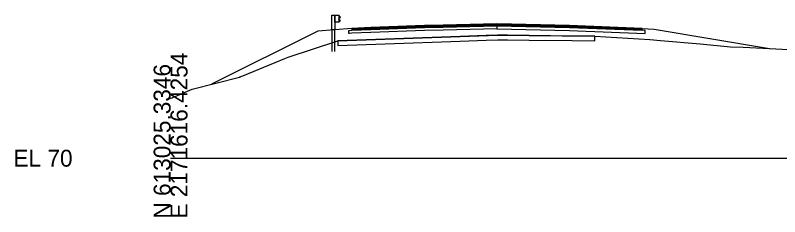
# Model space of a CAD drawing. Extents: x -26 to 1303, y -3010 to 12023.
# Drawn here: x -25.7 to 100.8, y 4990.3 to 5023.7 of the extents above; entities that cross this region are included whole.
import ezdxf

# ---------------------------------------------------------------- set-up
doc = ezdxf.new("R2010")
doc.units = 0
for name, color, linetype in [('RD_GPK_XS_Cell', 7, 'Continuous'), ('RD_PD_Final_TrvlWay', 7, 'Continuous'), ('RD_XS_Base', 7, 'Continuous'), ('RD_XS_ExGround', 7, 'Continuous'), ('RD_XS_ExPaveRet', 7, 'Continuous'), ('RD_XS_GR', 7, 'Continuous'), ('RD_XS_Greenside', 7, 'Continuous'), ('RD_XS_Pave', 7, 'Continuous'), ('RD_XS_PaveOvlay_CP', 7, 'Continuous'), ('RD_XS_TieSlope', 7, 'Continuous')]:
    doc.layers.add(name, color=color, linetype=linetype)

msp = doc.modelspace()

# ---------------------------------------------------------------- linework, layer by layer
at = {"layer": 'RD_GPK_XS_Cell'}
msp.add_line((0, 5000), (150, 5000), dxfattribs=at)
at = {"layer": 'RD_PD_Final_TrvlWay'}
msp.add_lwpolyline([(27.17, 5017.68), (27.17, 5021.28), (26.67, 5021.24), (26.67, 5017.68)], dxfattribs=at)
at = {"layer": 'RD_XS_Base'}
for p, q in [((29.5, 5020.8), (29.5, 5021.17)), ((29.5, 5021.17), (29.63, 5021.17)), ((29.63, 5021.17), (30, 5021.19)), ((30, 5021.19), (33.12, 5021.31)), ((33.12, 5021.31), (42, 5021.67)), ((42, 5021.17), (33.12, 5020.81)), ((42, 5021.67), (45.12, 5021.73)), ((45.12, 5021.23), (42, 5021.17)), ((45.12, 5021.73), (54, 5021.91)), ((54, 5021.41), (45.12, 5021.23)), ((54, 5021.95), (54, 5022.07)), ((54, 5022.07), (54, 5021.58)), ((54, 5021.91), (54, 5022.07)), ((54, 5022.07), (54, 5021.41)), ((54, 5021.91), (54, 5021.95)), ((54, 5021.91), (54, 5021.54)), ((54, 5021.91), (54, 5021.41)), ((66, 5021.67), (54, 5021.91)), ((54, 5021.91), (54, 5021.91)), ((54, 5021.58), (54, 5021.41)), ((54, 5021.54), (54, 5021.41)), ((54, 5021.41), (54, 5021.41)), ((54, 5021.41), (54, 5021.41)), ((54, 5021.41), (66, 5021.17)), ((78, 5021.19), (66, 5021.67)), ((66, 5021.17), (78.5, 5020.67)), ((68, 5021.59), (68, 5021.59)), ((78.5, 5021.17), (78, 5021.19)), ((78, 5021.19), (78, 5021.19)), ((78.5, 5020.67), (78.5, 5021.17)), ((78.5, 5021.17), (78.5, 5021.17)), ((29.5, 5020.67), (29.5, 5020.8)), ((29.63, 5020.67), (29.5, 5020.67)), ((30, 5020.69), (29.63, 5020.67)), ((33.12, 5020.81), (30, 5020.69)), ((68, 5021.09), (68, 5021.09)), ((78.5, 5020.67), (78.5, 5020.67)), ((78.5, 5020.67), (78.5, 5020.67))]:
    msp.add_line(p, q, dxfattribs=at)
at = {"layer": 'RD_XS_ExGround'}
msp.add_lwpolyline([(0, 5009.88), (3.56, 5011.44), (11.39, 5013.44), (11.48, 5013.46), (11.57, 5013.48), (11.61, 5013.51), (11.97, 5013.65), (17.3, 5015.84), (18.9, 5016.5), (19.46, 5016.71), (27.65, 5019.42), (47.94, 5020.15), (54.12, 5020.38), (59.35, 5020.32), (70.22, 5020.19), (79.28, 5019.64), (81.06, 5019.49), (87.61, 5018.94), (92.64, 5018.46), (94.72, 5018.38), (104.46, 5017.9)], dxfattribs=at)
at = {"layer": 'RD_XS_ExPaveRet'}
msp.add_lwpolyline([(59.35, 5020.32), (55.73, 5020.36), (54.12, 5020.38), (52.21, 5020.31), (47.94, 5020.15), (35.5, 5019.7), (27.65, 5019.42), (27.65, 5019.01), (27.65, 5018.67), (35.5, 5018.95), (47.94, 5019.4), (52.21, 5019.56), (54.12, 5019.63), (55.73, 5019.61), (59.35, 5019.57), (66.45, 5019.49), (70.22, 5019.44), (70.22, 5019.79), (70.22, 5020.19), (66.45, 5020.24), (59.35, 5020.32)], dxfattribs=at)
msp.add_lwpolyline([(59.35, 5020.32), (55.73, 5020.36), (54.12, 5020.38), (52.21, 5020.31), (47.94, 5020.15), (35.5, 5019.7), (27.65, 5019.42), (27.65, 5019.01), (27.65, 5018.67), (35.5, 5018.95), (47.94, 5019.4), (52.21, 5019.56), (54.12, 5019.63), (55.73, 5019.61), (59.35, 5019.57), (66.45, 5019.49), (70.22, 5019.44), (70.22, 5019.79), (70.22, 5020.19), (66.45, 5020.24), (59.35, 5020.32)], dxfattribs=at)
at = {"layer": 'RD_XS_GR'}
for p, q in [((26.67, 5021.24), (26.67, 5023.68)), ((26.67, 5023.68), (26.92, 5023.68)), ((26.92, 5023.68), (27.17, 5023.68)), ((27.17, 5023.68), (27.17, 5021.28)), ((27.17, 5022.51), (27.17, 5023.68)), ((27.17, 5023.68), (27.83, 5023.68)), ((27.83, 5023.68), (27.83, 5022.51)), ((28.03, 5023.46), (27.83, 5023.68)), ((27.83, 5023.68), (27.83, 5022.81)), ((27.83, 5022.51), (27.17, 5022.51)), ((27.83, 5023.09), (27.9, 5023.17)), ((28.03, 5022.88), (27.83, 5023.09)), ((27.83, 5022.81), (27.83, 5022.51)), ((27.83, 5022.51), (27.9, 5022.58)), ((27.9, 5023.17), (28.1, 5023.38)), ((27.9, 5022.58), (28.1, 5022.8)), ((28.1, 5023.38), (28.03, 5023.46)), ((28.1, 5022.8), (28.03, 5022.88)), ((27.17, 5021.28), (26.67, 5021.24))]:
    msp.add_line(p, q, dxfattribs=at)
at = {"layer": 'RD_XS_Greenside'}
for p, q in [((80, 5021.35), (99.09, 5018.16)), ((24.35, 5021.06), (6.79, 5012.28))]:
    msp.add_line(p, q, dxfattribs=at)
at = {"layer": 'RD_XS_Pave'}
for p, q in [((33.12, 5021.63), (30, 5021.51)), ((30, 5021.51), (30, 5021.39)), ((33.12, 5021.47), (30, 5021.35)), ((30, 5021.35), (33.12, 5021.47)), ((30, 5021.39), (30, 5021.35)), ((30, 5021.35), (30, 5021.23)), ((30, 5021.19), (33.12, 5021.31)), ((30, 5021.23), (30, 5021.19)), ((42, 5021.99), (33.12, 5021.63)), ((42, 5021.83), (33.12, 5021.47)), ((33.12, 5021.47), (42, 5021.83)), ((33.12, 5021.31), (42, 5021.67)), ((45.12, 5022.05), (42, 5021.99)), ((45.12, 5021.89), (42, 5021.83)), ((42, 5021.83), (45.12, 5021.89)), ((42, 5021.67), (45.12, 5021.73)), ((54, 5022.23), (45.12, 5022.05)), ((54, 5022.07), (45.12, 5021.89)), ((45.12, 5021.89), (54, 5022.07)), ((45.12, 5021.73), (54, 5021.91)), ((66, 5021.99), (54, 5022.23)), ((54, 5021.95), (54, 5022.07)), ((54, 5022.07), (54, 5021.95)), ((54, 5021.91), (54, 5022.07)), ((54, 5022.07), (66, 5021.83)), ((66, 5021.83), (54, 5022.07)), ((54, 5022.07), (54, 5021.91)), ((54, 5021.91), (54, 5021.95)), ((54, 5021.95), (54, 5021.91)), ((54, 5021.91), (54, 5021.91)), ((54, 5021.91), (54, 5021.91)), ((54, 5021.91), (66, 5021.67)), ((78, 5021.51), (66, 5021.99)), ((66, 5021.83), (78, 5021.35)), ((78, 5021.35), (66, 5021.83)), ((66, 5021.67), (78, 5021.19)), ((68, 5021.91), (68, 5021.91)), ((68, 5021.75), (68, 5021.75)), ((68, 5021.75), (68, 5021.75)), ((68, 5021.59), (68, 5021.59)), ((78, 5021.35), (78, 5021.51)), ((78, 5021.51), (78, 5021.51)), ((78, 5021.35), (78, 5021.35)), ((78, 5021.35), (78, 5021.35)), ((78, 5021.19), (78, 5021.35)), ((78, 5021.35), (78, 5021.35)), ((78, 5021.19), (78, 5021.19)), ((78, 5021.19), (78, 5021.19))]:
    msp.add_line(p, q, dxfattribs=at)
at = {"layer": 'RD_XS_PaveOvlay_CP'}
for p, q in [((30, 5021.51), (42, 5021.99)), ((42, 5021.99), (54, 5022.23)), ((54, 5022.23), (66, 5021.99)), ((66, 5021.99), (78, 5021.51))]:
    msp.add_line(p, q, dxfattribs=at)
at = {"layer": 'RD_XS_TieSlope'}
for p, q in [((30, 5021.51), (24.35, 5021.06)), ((78, 5021.51), (80, 5021.35))]:
    msp.add_line(p, q, dxfattribs=at)

# ---------------------------------------------------------------- texts
at = {"layer": 'RD_GPK_XS_Cell'}
for s, p in [('E 2171616.4254', (2.8, 4990)), ('N 613025.3346', (0, 4990))]:
    msp.add_text(s, height=2.8, rotation=90, dxfattribs=at).set_placement(p)
msp.add_text('EL 70', height=2.8, dxfattribs=at).set_placement((-26, 4998.6))

doc.saveas('drawing.dxf')
